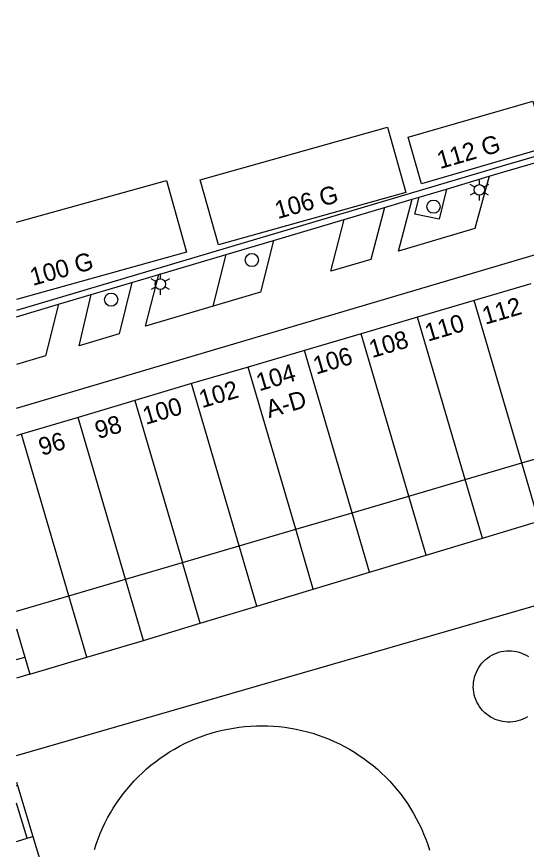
# Model space of a CAD drawing. Extents: x 122462 to 123306, y 485548 to 486417.
# Drawn here: x 122462 to 122505.2, y 486288.9 to 486359.4 of the extents above; entities that cross this region are included whole.
import ezdxf

# ---------------------------------------------------------------- set-up
doc = ezdxf.new("R2010")
doc.units = 0
for name, color, linetype in [('B-WE-IE-MEUBILAIR_WEGMEUBILAIR_VERKEERSBORD-S', 7, 'Continuous'), ('Level 1', 7, 'Continuous'), ('Level 10', 7, 'Continuous'), ('Level 12', 7, 'Continuous'), ('Level 15', 7, 'Continuous'), ('Level 17', 7, 'Continuous'), ('Level 19', 7, 'Continuous'), ('Level 2', 7, 'Continuous'), ('Level 21', 7, 'Continuous'), ('Level 22', 7, 'Continuous'), ('Level 4', 7, 'Continuous'), ('Level 50', 7, 'Continuous'), ('Level 53', 7, 'Continuous'), ('N werkgrens', 7, 'Continuous')]:
    doc.layers.add(name, color=color, linetype=linetype)

msp = doc.modelspace()

# ---------------------------------------------------------------- linework, layer by layer
at = {"layer": 'Level 1'}
for p, q in [((122505.584, 486336.761), (122500.795, 486335.351)), ((122500.795, 486335.351), (122496.006, 486333.941)), ((122496.006, 486333.941), (122491.217, 486332.53)), ((122491.217, 486332.53), (122486.428, 486331.12)), ((122486.428, 486331.12), (122481.639, 486329.71)), ((122481.639, 486329.71), (122476.85, 486328.299)), ((122476.85, 486328.299), (122472.043, 486326.87)), ((122472.043, 486326.87), (122467.237, 486325.44)), ((122467.237, 486325.44), (122462.429, 486324.009)), ((122462.429, 486324.009), (122462.03, 486323.893)), ((122504.835, 486321.584), (122509.625, 486322.99)), ((122500.045, 486320.179), (122504.835, 486321.584)), ((122495.255, 486318.772), (122500.045, 486320.179)), ((122490.465, 486317.367), (122495.255, 486318.772)), ((122485.675, 486315.961), (122490.465, 486317.367)), ((122480.885, 486314.555), (122485.675, 486315.961)), ((122476.071, 486313.143), (122480.885, 486314.555)), ((122471.261, 486311.731), (122476.071, 486313.143)), ((122466.449, 486310.319), (122471.261, 486311.731)), ((122462.03, 486309.022), (122466.449, 486310.319)), ((122462.92, 486289.797), (122463.413, 486289.945))]:
    msp.add_line(p, q, dxfattribs=at)
for points in [[(122468.612, 486288.833), (122468.761, 486289.294), (122468.926, 486289.751), (122469.106, 486290.201), (122469.3, 486290.646), (122469.508, 486291.084), (122469.731, 486291.515), (122469.968, 486291.938), (122470.218, 486292.354), (122470.482, 486292.761), (122470.759, 486293.159), (122471.049, 486293.548), (122471.352, 486293.927), (122471.667, 486294.296), (122471.993, 486294.655), (122472.331, 486295.003), (122472.681, 486295.339), (122473.041, 486295.664), (122473.411, 486295.977), (122473.792, 486296.278), (122474.182, 486296.566), (122474.582, 486296.841), (122474.99, 486297.104), (122475.407, 486297.352), (122475.831, 486297.587), (122476.263, 486297.808), (122476.702, 486298.014), (122477.148, 486298.206), (122477.599, 486298.384), (122478.056, 486298.546), (122478.518, 486298.694), (122478.985, 486298.826), (122479.456, 486298.944), (122479.93, 486299.045), (122480.407, 486299.131), (122480.887, 486299.202), (122481.369, 486299.256), (122481.853, 486299.295), (122482.338, 486299.318), (122482.823, 486299.326), (122483.308, 486299.317), (122483.792, 486299.293), (122484.276, 486299.252), (122484.758, 486299.196), (122485.237, 486299.124), (122485.714, 486299.037), (122486.189, 486298.934), (122486.659, 486298.816), (122487.125, 486298.682), (122487.587, 486298.533), (122488.044, 486298.369), (122488.495, 486298.19), (122488.94, 486297.997), (122489.378, 486297.789), (122489.809, 486297.567), (122490.233, 486297.331), (122490.649, 486297.082), (122491.056, 486296.818), (122491.455, 486296.542), (122491.845, 486296.253), (122492.224, 486295.951), (122492.594, 486295.637), (122492.953, 486295.311), (122493.302, 486294.973), (122493.639, 486294.624), (122493.965, 486294.265), (122494.278, 486293.895), (122494.58, 486293.515), (122494.869, 486293.125), (122495.145, 486292.726), (122495.407, 486292.318), (122495.657, 486291.902), (122495.892, 486291.478), (122496.114, 486291.046), (122496.321, 486290.608), (122496.514, 486290.163), (122496.692, 486289.712), (122496.856, 486289.255), (122497.004, 486288.793)], [(122462.03, 486289.529), (122462.92, 486289.797)], [(122463.413, 486289.945), (122465.586, 486282.778)]]:
    msp.add_lwpolyline(points, dxfattribs=at)
at = {"layer": 'Level 10'}
msp.add_lwpolyline([(122462.03, 486294.535), (122462.114, 486294.255), (122462.03, 486294.23)], dxfattribs=at)
at = {"layer": 'Level 12'}
for points in [[(122496.33, 486345.23), (122495.189, 486349.168), (122505.755, 486352.228), (122506.896, 486348.29), (122496.33, 486345.23)], [(122479.143, 486340.047), (122477.59, 486345.567), (122493.439, 486350.024), (122494.992, 486344.504), (122479.143, 486340.047)], [(122462.03, 486341.977), (122474.713, 486345.519), (122476.413, 486339.432), (122462.03, 486335.414)]]:
    msp.add_lwpolyline(points, dxfattribs=at)
at = {"layer": 'Level 15'}
for p, q in [((122498.442, 486344.786), (122502.076, 486345.866)), ((122496.131, 486344.1), (122498.442, 486344.786)), ((122493.191, 486343.226), (122495.533, 486343.922)), ((122495.533, 486343.922), (122496.131, 486344.1)), ((122489.784, 486342.215), (122493.191, 486343.226)), ((122483.791, 486340.435), (122489.784, 486342.215)), ((122479.778, 486339.243), (122483.791, 486340.435)), ((122474.068, 486337.547), (122479.778, 486339.243)), ((122471.778, 486336.867), (122474.068, 486337.547)), ((122468.344, 486335.847), (122471.778, 486336.867)), ((122465.573, 486335.023), (122468.344, 486335.847)), ((122462.03, 486333.971), (122465.573, 486335.023))]:
    msp.add_line(p, q, dxfattribs=at)
for points in [[(122548.544, 486359.909), (122503.438, 486346.792), (122462.03, 486334.493)], [(122502.076, 486345.866), (122502.828, 486346.089), (122503.579, 486346.312), (122510.508, 486348.327)]]:
    msp.add_lwpolyline(points, dxfattribs=at)
at = {"layer": 'Level 17'}
msp.add_line((122478.685, 486334.871), (122479.778, 486339.243), dxfattribs=at)
for points in [[(122462.03, 486326.221), (122504.943, 486338.93), (122543.859, 486350.456)], [(122502.076, 486345.866), (122500.85, 486341.44), (122494.378, 486339.522), (122495.533, 486343.922)], [(122498.442, 486344.786), (122497.827, 486342.232), (122495.776, 486342.658), (122496.131, 486344.1)], [(122493.191, 486343.226), (122492.041, 486338.829), (122488.638, 486337.821), (122489.784, 486342.215)], [(122483.791, 486340.435), (122482.697, 486336.06), (122478.685, 486334.871)], [(122478.685, 486334.871), (122472.951, 486333.171), (122474.068, 486337.547)], [(122471.778, 486336.867), (122470.723, 486332.511), (122467.325, 486331.504), (122468.344, 486335.847)], [(122465.573, 486335.023), (122464.486, 486330.662), (122462.03, 486329.934)]]:
    msp.add_lwpolyline(points, dxfattribs=at)
at = {"layer": 'Level 19'}
for p, q in [((122506.279, 486316.661), (122504.835, 486321.584)), ((122501.5, 486315.222), (122500.045, 486320.179)), ((122496.72, 486313.782), (122495.255, 486318.772)), ((122491.939, 486312.343), (122490.465, 486317.367)), ((122487.161, 486310.9), (122485.675, 486315.961)), ((122482.382, 486309.456), (122480.885, 486314.555)), ((122477.578, 486308.004), (122476.071, 486313.143)), ((122472.779, 486306.558), (122471.261, 486311.731)), ((122467.972, 486305.129), (122466.449, 486310.319)), ((122462.03, 486307.526), (122462.728, 486305.136))]:
    msp.add_line(p, q, dxfattribs=at)
at = {"layer": 'Level 2'}
for p, q in [((122462.728, 486305.136), (122463.155, 486303.698)), ((122463.155, 486303.698), (122462.03, 486303.363))]:
    msp.add_line(p, q, dxfattribs=at)
msp.add_lwpolyline([(122462.03, 486304.928), (122462.728, 486305.136)], dxfattribs=at)
at = {"layer": 'Level 21'}
for points in [[(122462.03, 486294.23), (122462.114, 486294.255), (122463.413, 486289.945)], [(122462.92, 486289.797), (122462.03, 486292.753)]]:
    msp.add_lwpolyline(points, dxfattribs=at)
at = {"layer": 'Level 22'}
for points in [[(122503.855, 486299.634), (122503.636, 486299.634), (122503.419, 486299.65), (122503.203, 486299.681), (122502.99, 486299.728), (122502.78, 486299.79), (122502.576, 486299.867), (122502.378, 486299.959), (122502.187, 486300.064), (122502.004, 486300.183), (122501.83, 486300.315), (122501.667, 486300.46), (122501.514, 486300.615), (122501.372, 486300.782), (122501.243, 486300.958), (122501.127, 486301.143), (122501.025, 486301.335), (122500.937, 486301.535), (122500.863, 486301.741), (122500.805, 486301.951), (122500.762, 486302.165), (122500.734, 486302.381), (122500.722, 486302.599), (122500.726, 486302.817), (122500.746, 486303.035), (122500.781, 486303.25), (122500.832, 486303.463), (122500.897, 486303.671), (122500.978, 486303.873), (122501.073, 486304.07), (122501.182, 486304.259), (122501.305, 486304.44), (122501.44, 486304.611), (122501.587, 486304.772), (122501.745, 486304.922), (122501.914, 486305.061), (122502.093, 486305.187), (122502.279, 486305.299), (122502.474, 486305.398), (122502.675, 486305.482), (122502.882, 486305.552), (122503.093, 486305.607), (122503.308, 486305.646), (122503.525, 486305.67), (122503.745, 486305.678), (122503.963, 486305.67), (122504.18, 486305.646), (122504.395, 486305.607), (122504.606, 486305.553), (122504.813, 486305.483), (122505.014, 486305.399), (122505.209, 486305.3), (122505.396, 486305.187)], [(122505.304, 486300.065), (122505.113, 486299.959), (122504.915, 486299.868), (122504.711, 486299.79), (122504.501, 486299.728), (122504.288, 486299.681), (122504.072, 486299.65), (122503.855, 486299.634)]]:
    msp.add_lwpolyline(points, dxfattribs=at)
at = {"layer": 'Level 4'}
for p, q in [((122504.835, 486321.584), (122500.795, 486335.351)), ((122500.045, 486320.179), (122496.006, 486333.941)), ((122495.255, 486318.772), (122491.217, 486332.53)), ((122490.465, 486317.367), (122486.428, 486331.12)), ((122485.675, 486315.961), (122481.639, 486329.71)), ((122480.885, 486314.555), (122476.85, 486328.299)), ((122472.043, 486326.87), (122476.071, 486313.143)), ((122471.261, 486311.731), (122467.237, 486325.44)), ((122466.449, 486310.319), (122462.429, 486324.009))]:
    msp.add_line(p, q, dxfattribs=at)
at = {"layer": 'Level 50'}
for p, q in [((122500.847, 486344.935), (122500.457, 486345.16)), ((122501.237, 486345.16), (122501.237, 486345.61)), ((122502.016, 486345.16), (122501.626, 486344.935)), ((122500.847, 486344.485), (122500.457, 486344.26)), ((122501.237, 486343.81), (122501.237, 486344.26)), ((122502.016, 486344.26), (122501.626, 486344.485)), ((122474.205, 486337.173), (122474.205, 486337.623)), ((122473.815, 486336.948), (122473.425, 486337.173)), ((122473.815, 486336.498), (122473.425, 486336.273)), ((122474.984, 486337.173), (122474.594, 486336.948)), ((122474.984, 486336.273), (122474.594, 486336.498)), ((122474.205, 486335.823), (122474.205, 486336.273))]:
    msp.add_line(p, q, dxfattribs=at)
for centre in [(122501.237, 486344.71), (122474.205, 486336.723)]:
    msp.add_circle(centre, 0.45, dxfattribs=at)
at = {"layer": 'Level 53'}
for centre in [(122497.343, 486343.29), (122481.96, 486338.772), (122470.033, 486335.415)]:
    msp.add_circle(centre, 0.56, dxfattribs=at)
at = {"layer": 'N werkgrens'}
for p, q in [((122501.5, 486315.222), (122506.279, 486316.661)), ((122496.72, 486313.782), (122501.5, 486315.222)), ((122491.939, 486312.343), (122496.72, 486313.782)), ((122487.161, 486310.9), (122491.939, 486312.343)), ((122462.03, 486296.791), (122509.741, 486310.586)), ((122482.382, 486309.456), (122487.161, 486310.9)), ((122477.578, 486308.004), (122482.382, 486309.456)), ((122472.779, 486306.558), (122477.578, 486308.004)), ((122467.972, 486305.129), (122472.779, 486306.558)), ((122463.155, 486303.698), (122467.972, 486305.129))]:
    msp.add_line(p, q, dxfattribs=at)

# ---------------------------------------------------------------- texts
at = {"layer": 'B-WE-IE-MEUBILAIR_WEGMEUBILAIR_VERKEERSBORD-S'}
for s, rotation, p in [('112 G', 16.15145, (122497.9, 486346.466)), ('106 G', 15.70686, (122484.153, 486342.235)), ('100 G', 15.60776, (122463.401, 486336.576)), ('112', 16.3905, (122501.734, 486333.283)), ('110', 16.3905, (122496.877, 486331.853)), ('108', 16.3905, (122492.147, 486330.461)), ('106', 16.3905, (122487.406, 486329.064)), ('104', 16.3905, (122482.584, 486327.645)), ('102', 16.3905, (122477.742, 486326.218)), ('A-D', 16.4073, (122483.405, 486325.374)), ('100', 16.3905, (122472.97, 486324.806)), ('98', 16.3905, (122468.924, 486323.599)), ('96', 16.3905, (122464.152, 486322.18))]:
    msp.add_text(s, height=1.5, rotation=rotation, dxfattribs=at).set_placement(p)

doc.saveas('drawing.dxf')
